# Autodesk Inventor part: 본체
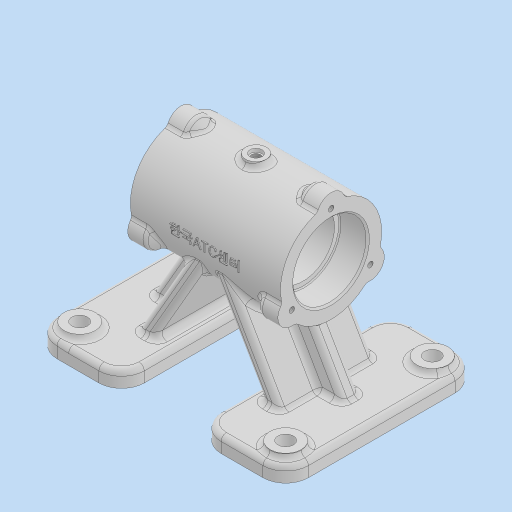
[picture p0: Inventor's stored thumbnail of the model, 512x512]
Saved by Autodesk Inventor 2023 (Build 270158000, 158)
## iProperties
Created: 2026-04
Part Number: 본체
Material: 일반
Document SubType Name: Modeling
Designer: home
Density: 1 g/cm^3
Appearance: 기본값
Author: home
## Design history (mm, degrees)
sketch "스케치2"
  geometry: L1 (-43, 29)-(43, 29); L2 (43, 29)-(43, 0); L3 (43, 0)-(-43, 0); L4 (-43, 0)-(-43, 29); 2 further points
  constraints: 8 end point, 2 parallel, 1 coincident, 1 horizontal, 1 midpoint, 1 perpendicular
  dimensions: "d0" = 86 distance of L1.start L1.end; "d1" = 58 diameter of L1 L3
revolve "회전1" sketch "스케치2" stored, may be unused: angle "d6" = 90 deg
node "작업 평면1"
sketch "스케치3"
  geometry: L1 (72, 55)-(22, 55); L2 (22, 55)-(22, -55); L3 (22, -55)-(72, -55); L4 (72, -55)-(72, 55); L5 (72, 55)-(22, -55); L6 (22, 55)-(72, -55); L7 (-22, 55)-(-72, 55); L8 (-72, 55)-(-72, -55); L9 (-72, -55)-(-22, -55); L10 (-22, -55)-(-22, 55); L11 (-22, 55)-(-72, -55); L12 (-72, 55)-(-22, -55); 4 further points
  constraints: 24 end point, 5 midpoint, 4 parallel, 2 collinear, 2 horizontal, 2 perpendicular, 1 horizontal alignment
  dimensions: "d8" = 144 distance between parallel lines of L8 L4; "d9" = 110 distance of L3.end L1.start; "d11" = 50 distance of L1.start L1.end; "d12" = 50 distance of L7.start L7.end; "d13" = 72 distance of point (72, 0) point (0, 0) (= 0.5 x d8)
extrude "돌출1" join sketch "스케치3" distance "d14" = 9; taper "d15" = 0 deg
fillet "모깎기1" dims "d16" = 13
node "작업 평면2"
sketch "스케치6"
  geometry: L1 (43, 10.583)-(43, -10.583) reference; L2 (43, -10.583)-(-43, -10.583) reference; L3 (-43, -10.583)-(-43, 10.583) reference; L4 (-43, 10.583)-(43, 10.583) reference; L5 (22, -63)-(72, -63) reference; L6 (72, -63)-(72, -72) reference; L7 (72, -72)-(22, -72) reference; L8 (22, -72)-(22, -63) reference; L9 (-72, -72)-(-72, -63) reference; L10 (-72, -63)-(-22, -63) reference; L11 (-22, -63)-(-22, -72) reference; L12 (-22, -72)-(-72, -72) reference; L13 (1.737, -10.583)-(32, -63); L14 (59, -63)-(35, -63) reference; L15 (41.238, -63)-(10.975, -10.583); 3 further points
  constraints: 4 end point, 4 point on line, 1 parallel
  dimensions: "d25" = 30 deg angle of L3 L13; "d26" = 10 distance of L5.start L13.end; "d27" = 8 distance between parallel lines of L13 L15
extrude "돌출3" join sketch "스케치6" distance "d28" = 54; taper "d29" = 0 deg
sketch "스케치7"
  geometry: L1 (-72, -72)-(-72, -63) reference; L2 (-72, -63)-(-22, -63) reference; L3 (-22, -63)-(-22, -72) reference; L4 (-22, -72)-(-72, -72) reference; L5 (43, 29)-(43, -29) reference; L6 (43, -29)-(21.608, -29) reference; L7 (21.608, -29)-(41.238, -63) reference; L8 (41.238, -63)-(72, -63) reference; L9 (72, -63)-(72, -72) reference; L10 (72, -72)-(22, -72) reference; L11 (22, -72)-(22, -63) reference; L12 (22, -63)-(32, -63) reference; L13 (32, -63)-(12.37, -29) reference; L14 (12.37, -29)-(-43, -29) reference; L15 (-43, -29)-(-43, 29) reference; L16 (-43, 29)-(43, 29) reference; L17 (59, -63)-(35, -63) reference; L18 (43, -29)-(-43, -29) reference; L19 (55.094, -63)-(18.721, 0); L20 (41.238, -63)-(10.975, -10.583) reference; 1 further point
  constraints: 2 end point, 1 horizontal alignment, 1 parallel, 1 point on line
  dimensions: "d31" = 12 distance between parallel lines of L20 L19
feature "리브1" sketch "스케치7" dims "d32" = 12, "d33" = 10, "d34" = 0, "d35" = 0, "d36" = 1, "d37" = 1
sketch "스케치10"
  geometry: L1 (-32, 27)-(-32, -27) reference; L2 (-32, -27)-(-41.238, -27) reference; L3 (-41.238, -27)-(-41.238, -5) reference; L4 (-41.238, -5)-(-55.094, -5) reference; L5 (-55.094, -5)-(-55.094, 5) reference; L6 (-55.094, 5)-(-41.238, 5) reference; L7 (-41.238, 5)-(-41.238, 27) reference; L8 (-41.238, 27)-(-32, 27) reference; L9 (32, -27)-(32, 27) reference; L10 (32, 27)-(41.238, 27) reference; L11 (41.238, 27)-(41.238, 5) reference; L12 (41.238, 5)-(55.094, 5) reference; L13 (55.094, 5)-(55.094, -5) reference; L14 (55.094, -5)-(41.238, -5) reference; L15 (41.238, -5)-(41.238, -27) reference; L16 (41.238, -27)-(32, -27) reference; L17 (22, -42)-(22, 42) reference; L18 (35, 55)-(59, 55) reference; L19 (72, 42)-(72, -42) reference; L20 (59, -55)-(35, -55) reference; L21 (-22, 42)-(-22, -42) reference; L22 (-35, -55)-(-59, -55) reference; L23 (-72, -42)-(-72, 42) reference; L24 (-59, 55)-(-35, 55) reference; C1 r 9 at (-59, 42); C2 r 9 at (-59, -42); C3 r 9 at (59, 42); C4 r 9 at (59, -42); A1 r 13 centre (35, -42) between (22, -42) and (35, -55) reference; A2 r 13 centre (35, 42) between (35, 55) and (22, 42) reference; A3 r 13 centre (59, 42) between (72, 42) and (59, 55) reference; A4 r 13 centre (59, -42) between (59, -55) and (72, -42) reference; A5 r 13 centre (-35, 42) between (-22, 42) and (-35, 55) reference; A6 r 13 centre (-35, -42) between (-35, -55) and (-22, -42) reference; A7 r 13 centre (-59, -42) between (-72, -42) and (-59, -55) reference; A8 r 13 centre (-59, 42) between (-59, 55) and (-72, 42) reference
  constraints: 4 centre point, 4 coincident
  dimensions: "d52" = 18 diameter of C1; "d54" = 18 diameter of C2; "d57" = 18 diameter of C4; "d59" = 18 diameter of C3
extrude "돌출4" join sketch "스케치10" distance "d60" = 3; taper "d61" = 0 deg
sketch "스케치11"
  geometry: C1 r 9 at (0, 0) reference; C2 r 9 at (0, -84) reference; C3 r 9 at (118, -84) reference; C4 r 9 at (118, 0) reference; 5 further points
  constraints: 4 coincident
hole "구멍3" sketch "스케치11" at (0, 0), (0, -84), (118, -84), (118, 0) diameter "d62" = 9; stored, may be unused: countersink angle "d66" = 90 deg, drill point angle "d68" = 0 deg; dims "d63" = 6, "d64" = 42, "d65" = 16, "d67" = 8
sketch "스케치12"
  geometry: L1 (43, 29)-(-43, 29) reference; L2 (43, 29)-(43, -29) reference; L3 (43, 26)-(-43, 26); L4 (-43, 29)-(-43, -29) reference; L5 (25, 26)-(33, 34); L6 (33, 34)-(43, 34); L7 (43, 34)-(43, 26); 3 further points
  constraints: 8 end point, 3 point on line, 2 horizontal, 1 perpendicular
  dimensions: "d70" = 26 distance from line of L3 point (0, 0); "d71" = 45 deg angle of L4 L5; "d72" = 10 distance of L5.end L6.end; "d73" = 8 distance of L6.end L3.start
revolve "회전2" sketch "스케치12" stored, may be unused: angle "d74" = 90 deg
sketch "스케치8"
  geometry: A1 r 29 centre (0, 0) between (-7.761, 27.942) and (7.761, 27.942) reference; 2 further points
  constraints: 1 coincident
hole "구멍1" sketch "스케치8" at (0, 0) diameter "d38" = 36; stored, may be unused: countersink angle "d42" = 90 deg, drill point angle "d44" = 0 deg; dims "d39" = 12, "d40" = 42, "d41" = 16, "d43" = 14
sketch "스케치9"
  geometry: A1 r 29 centre (0, 0) between (-7.761, 27.942) and (-28.079, -7.25) reference; 2 further points
  constraints: 1 coincident
hole "구멍2" sketch "스케치9" at (0, 0) diameter "d45" = 36; stored, may be unused: countersink angle "d49" = 90 deg, drill point angle "d51" = 0 deg; dims "d46" = 6, "d47" = 42, "d48" = 16, "d50" = 8
sketch "스케치13"
  geometry: A1 r 8 centre (0, 0) between (7.761, 1.942) and (-7.761, 1.942) reference; A2 r 8 centre (-22.517, -39) between (-28.079, -33.25) and (-20.318, -46.692) reference; A3 r 8 centre (22.517, -39) between (20.318, -46.692) and (28.079, -33.25) reference; 4 further points
  constraints: 3 coincident
hole "구멍4" sketch "스케치13" at (0, 0), (-22.517, -39), (22.517, -39) diameter "d78" = 3.242; stored, may be unused: countersink angle "d82" = 90 deg, drill point angle "d84" = 118 deg; dims "d79" = 8, "d80" = 4, "d81" = 2, "d83" = 10
sketch "스케치14"
  geometry: A1 r 8 centre (0, 26) between (7.761, 27.942) and (-7.761, 27.942) reference; A2 r 8 centre (22.517, -13) between (20.318, -20.692) and (28.079, -7.25) reference; A3 r 8 centre (-22.517, -13) between (-28.079, -7.25) and (-20.318, -20.692) reference; 4 further points
  constraints: 3 coincident
hole "구멍5" sketch "스케치14" at (0, 26), (22.517, -13), (-22.517, -13) diameter "d85" = 3.242; stored, may be unused: countersink angle "d89" = 90 deg, drill point angle "d91" = 118 deg; dims "d86" = 8, "d87" = 4, "d88" = 2, "d90" = 10
node "작업 평면4"
sketch "스케치15"
  geometry: C1 r 6 at (0, 0); 1 further point
  constraints: 1 centre point, 1 coincident
  dimensions: "d93" = 12 diameter of C1
extrude "돌출5" join sketch "스케치15" stored distance "d94" = 10; taper "d95" = 0 deg
sketch "스케치16"
  geometry: C1 r 6 at (0, 0) reference; 2 further points
  constraints: 1 coincident
hole "구멍6" sketch "스케치16" at (0, 0) diameter "d96" = 5.1881; stored, may be unused: countersink angle "d100" = 90 deg, drill point angle "d102" = 0 deg; dims "d97" = 12, "d98" = 7, "d99" = 2, "d101" = 10
fillet "모깎기4" dims "d105" = 3
fillet "모깎기2" dims "d103" = 3
fillet "모깎기3" dims "d104" = 3
fillet "모깎기5" dims "d106" = 0.6
chamfer "모따기1" distance "d107" = 1; stored, may be unused: second distance "d108" = 2, angle "d109" = 45 deg
node "작업 평면5"
sketch "스케치17"
  geometry: L1 (-59, -72)-(-35, -72) reference; 2 further points
  constraints: 1 coincident, 1 other
  dimensions: "d110" = 72 distance from line of L1 point (0, 0)
feature "엠보싱1" sketch "스케치17" dims "d0" = 86, "d1" = 58, "d111" = 0.5, "d112" = 0
node "솔리드1"
mirror "미러1"
pattern_circular "원형 패턴1" dims angle "d76" = 360 deg
mirror "미러2"
mirror "미러3"
node "절단 모서리 투영1"
node "절단 모서리 투영2"
node "절단 모서리 투영3"
feature "A9D066F2-1C7D-4E18-AEED-F7BC21143FA4" dims "d62" = 9, "d63" = 6, "d64" = 42, "d65" = 16, "d66" = 90 deg, "d67" = 8, "d68" = 0
other parameters: "d7" = -72, "d24" = 27, "d92" = 32
